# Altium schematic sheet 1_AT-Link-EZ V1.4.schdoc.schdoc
size 309 x 223 mm; Symbol: Artery_A4; Device: Artery_A4; @Page Count: 4; @Create Date: 2024-01-02; @Page Name: AT-Link-EZ V1.4; @Project Name: AT-START-L021; @Update Date: 2024-02-21; @Schematic Name: AT-START-L021_V1.0; @Page No: 1; Company: Artery Technology; Drawed: SD; Version: 1.0; Page Size: A4
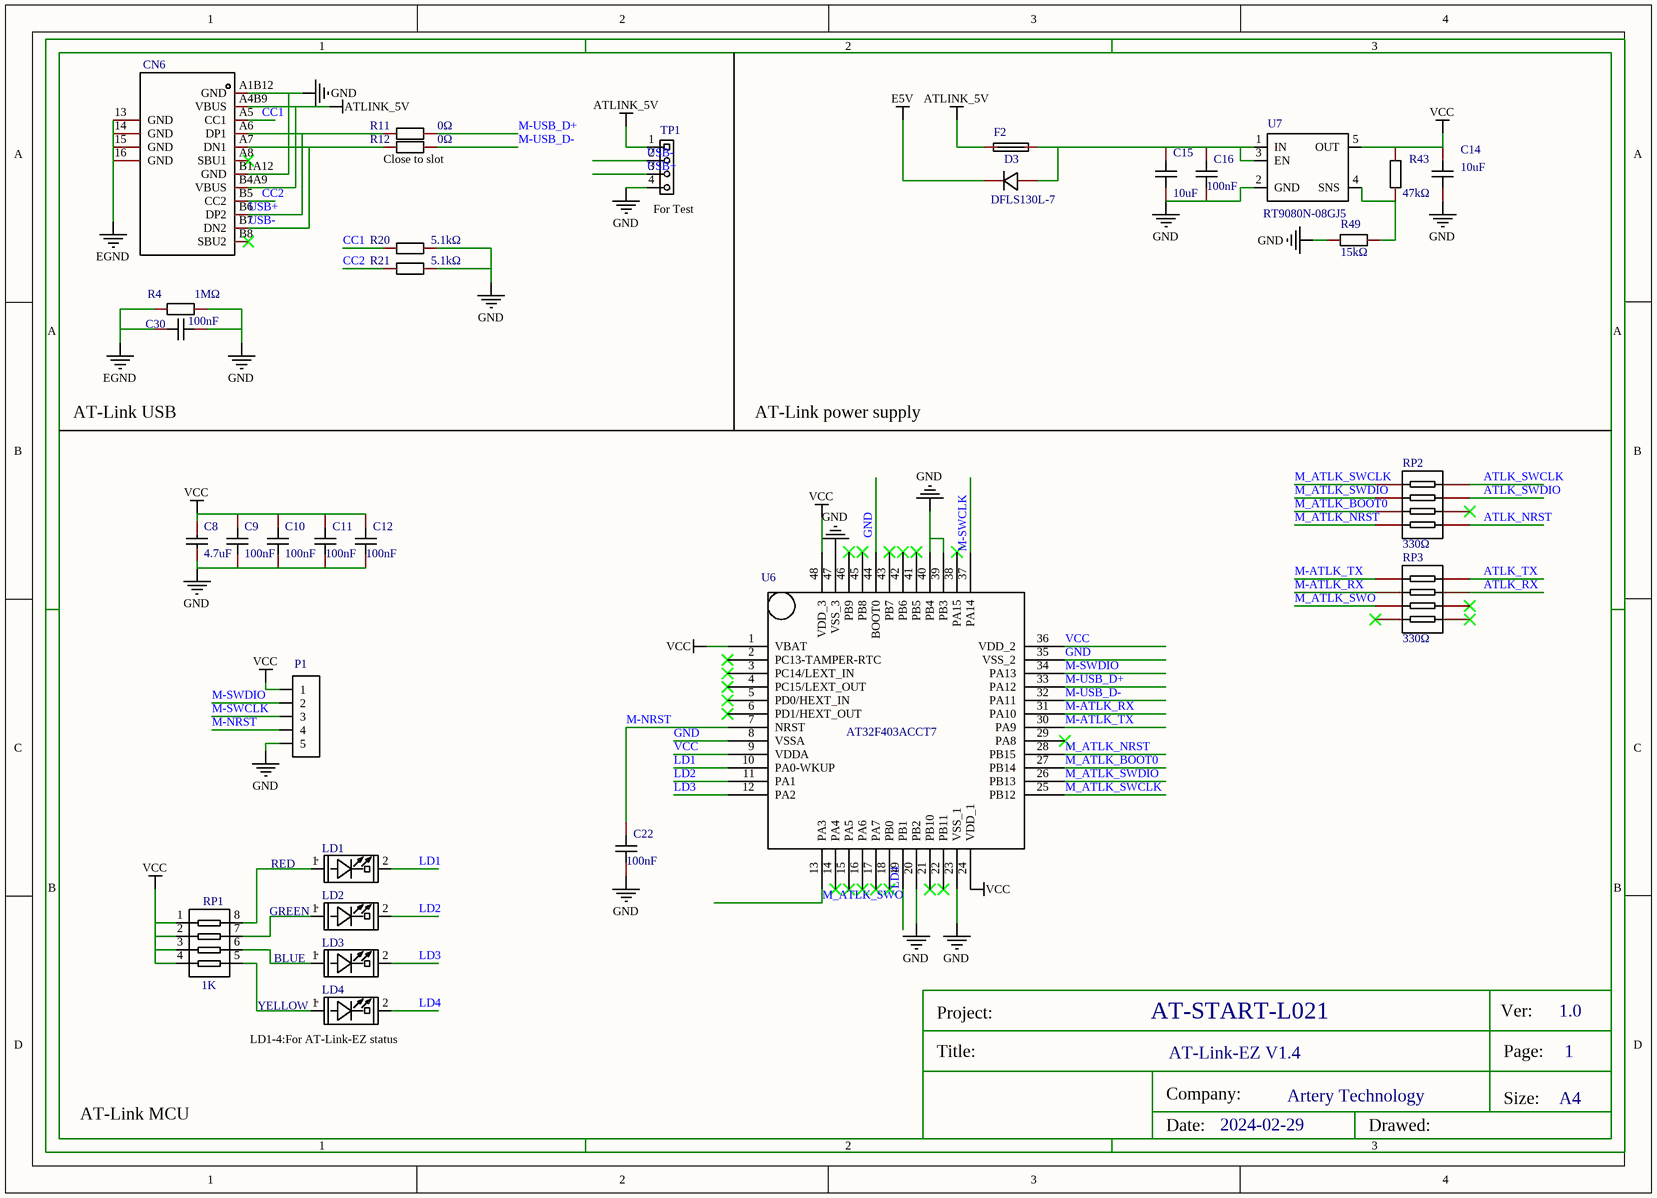
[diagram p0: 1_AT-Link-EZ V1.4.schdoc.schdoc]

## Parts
C8  value 4.7uF  [C0603]  (hidden comment: CL10A475KO8NNNC)
C9  value 100nF  [C0603]  (hidden comment: CC0603KRX7R9BB104)
C10  value 100nF  [C0603]  (hidden comment: CC0603KRX7R9BB104)
C11  value 100nF  [C0603]  (hidden comment: CC0603KRX7R9BB104)
C12  value 100nF  [C0603]  (hidden comment: CC0603KRX7R9BB104)
C14  value 10uF  [C0603]  (hidden comment: CL10A106KP8NNNC)
C15  value 10uF  [C0603]  (hidden comment: CL10A106KP8NNNC)
C16  value 100nF  [C0603]  (hidden comment: CC0603KRX7R9BB104)
C22  value 100nF  [C0603]  (hidden comment: CC0603KRX7R9BB104)
C30  value 100nF  [C0603]  (hidden comment: CC0603KRX7R9BB104)
CN6  TYPEC-304-BCP16  [USB-C-SMD_TYPEC-304-BCP16]  (value not drawn)
D3  DFLS130L-7  [POWERDI-123_L2.8-W1.8-LS3.7-RD]
F2  SMD0603B050TF  [R0603]  (value not drawn)
LD1  RED  [LED0603]
LD2  GREEN  [LED0603]
LD3  BLUE  [LED0603]
LD4  YELLOW  [LED0603]
P1  HDR-M-2.54_1x5  [HDR-M-2.54_1X5]  (value not drawn)
R4  value 1MΩ  [R0603]  (hidden comment: RC0603FR-071ML)
R11  value 0Ω  [R0603]  (hidden comment: 0603WAF0000T5E)
R12  value 0Ω  [R0603]  (hidden comment: 0603WAF0000T5E)
R20  value 5.1kΩ  [R0603]  (hidden comment: 0603WAF5101T5E)
R21  value 5.1kΩ  [R0603]  (hidden comment: 0603WAF5101T5E)
R43  value 47kΩ  [R0603]  (hidden comment: 0603WAF4702T5E)
R49  value 15kΩ  [R0603]  (hidden comment: 0603WAF1502T5E)
RP1  1K  [0603*4,8P4R]
RP2  value 330Ω  [RES-ARRAY-SMD_0603-8P-L3.2-W1.6-BL]  (hidden comment: 4D03WGJ0331T5E)
RP3  value 330Ω  [RES-ARRAY-SMD_0603-8P-L3.2-W1.6-BL]  (hidden comment: 4D03WGJ0331T5E)
TP1  1X4P_2.54F  [HDR1X4 - TOP]  (value not drawn)
U6  AT32F403ACCT7  [LQFP48 - 2]
U7  RT9080N-08GJ5  [SOT-23-5(1)]

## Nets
ATLINK_5V: CN6.A4B9(VBUS) CN6.B4A9(VBUS) F2.1 TP1.1
E5V: D3.1
EGND: C30.2 CN6.13(GND) CN6.14(GND) CN6.15(GND) CN6.16(GND) R4.1
GND: C8.1 C9.1 C10.1 C11.1 C12.1 C14.1 C15.1 C16.1 C22.1 C30.1 CN6.A1B12(GND) CN6.B1A12(GND) P1.5 R4.2 R20.2 R21.2 R49.1 TP1.4 U6.8(VSSA) U6.20(PB2) U6.23(VSS_1) U6.35(VSS_2) U6.39(PB3) U6.40(PB4) U6.44(BOOT0) U6.47(VSS_3) U7.2(GND)
VCC: C8.2 C9.2 C10.2 C11.2 C12.2 C14.2 P1.1 R43.2 RP1.1 RP1.2 RP1.3 RP1.4 U6.1(VBAT) U6.9(VDDA) U6.24(VDD_1) U6.36(VDD_2) U6.48(VDD_3) U7.5(OUT)
ATLK_NRST: RP2.4
ATLK_RX: RP3.2
ATLK_SWCLK: RP2.1
ATLK_SWDIO: RP2.2
ATLK_TX: RP3.1
CC1: CN6.A5(CC1) R20.1
CC2: CN6.B5(CC2) R21.1
LD1: LD1.2(CATHODE) U6.10(PA0-WKUP)
LD2: LD2.2(CATHODE) U6.11(PA1)
LD3: LD3.2(CATHODE) U6.12(PA2)
LD4: LD4.2(CATHODE) U6.19(PB1)
M-ATLK_RX: RP3.7 U6.31(PA10)
M-ATLK_TX: RP3.8 U6.30(PA9)
M-NRST: C22.2 P1.4 U6.7(NRST)
M-SWCLK: P1.3 U6.37(PA14)
M-SWDIO: P1.2 U6.34(PA13)
M-USB_D+: R11.2 U6.33(PA12)
M-USB_D-: R12.2 U6.32(PA11)
M_ATLK_BOOT0: RP2.6 U6.27(PB14)
M_ATLK_NRST: RP2.5 U6.28(PB15)
M_ATLK_SWCLK: RP2.8 U6.25(PB12)
M_ATLK_SWDIO: RP2.7 U6.26(PB13)
M_ATLK_SWO: RP3.6 U6.13(PA3)
USB+: CN6.A6(DP1) CN6.B6(DP2) R11.1 TP1.3
USB-: CN6.A7(DN1) CN6.B7(DN2) R12.1 TP1.2
NetC15_2: C15.2 C16.2 D3.2 F2.2 U7.1(IN) U7.3(EN)
NetLD1_1: LD1.1(ANODE) RP1.8
NetLD2_1: LD2.1(ANODE) RP1.7
NetLD3_1: LD3.1(ANODE) RP1.6
NetLD4_1: LD4.1(ANODE) RP1.5
NetR43_1: R43.1 R49.2 U7.4(SNS)

Not connected (* = marked no-connect by the designer): CN6 A8(SBU1)* B8(SBU2)*; RP2 3*; RP3 3* 4* 5*; U6 2(PC13-TAMPER-RTC)* 3(PC14/LEXT_IN)* 4(PC15/LEXT_OUT)* 5(PD0/HEXT_IN)* 6(PD1/HEXT_OUT)* 14(PA4)* 15(PA5)* 16(PA6)* 17(PA7)* 18(PB0)* 21(PB10)* 22(PB11)* 29(PA8)* 38(PA15)* 41(PB5)* 42(PB6)* 43(PB7)* 45(PB8)* 46(PB9)*

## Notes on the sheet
- (near R12) Close to slot
- (near TP1) For Test
- AT-Link USB
- AT-Link power supply
- (near LD4) LD1-4:For AT-Link-EZ status
- AT-Link MCU
- 2024-02-29

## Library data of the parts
C8 = CL10A475KO8NNNC: Manufacturer: SAMSUNG(三星); Add into BOM: yes; Tolerance: ±10%; Voltage Rated: 16V; Temperature Coefficient: X5R; Description: 容值:4.7uF;精度:±10%;额定电压:16V;温度系数:X5R;; Pin Type: IN
C9-C12 C16 C22 C30 = CC0603KRX7R9BB104: Manufacturer: YAGEO(国巨); Add into BOM: yes; Tolerance: ±10%; Voltage Rated: 50V; Temperature Coefficient: X7R; Description: 容值:100nF;精度:±10%;额定电压:50V;温度系数:X7R;; Pin Type: IN
C14 C15 = CL10A106KP8NNNC: Manufacturer: SAMSUNG(三星); Add into BOM: yes; Tolerance: ±10%; Voltage Rated: 10V; Temperature Coefficient: X5R; Description: 容值:10uF;精度:±10%;额定电压:10V;温度系数:X5R;; Pin Type: IN
CN6 = TYPEC-304-BCP16: 连接器类型:Type-C;标准:USB 3.1;公母:母座;触点数量:16.0;端口数量:1;安装方式:卧贴;额定电流 - 电源:3A;工作温度范围:-25~+85;焊接温度(最大值):260;; Manufacturer: XUNPU(讯普); Add into BOM: yes; Connector Type: Type-C; Gender: 母座; Number of Contacts: 16.0; Number of Ports: 1; Mounting Sytle: 卧贴; Current Rating - Power (Max): 3A; Welding Temperature (Max): 260; Pin Type: IN
D3 = DFLS130L-7_POWERDI-123_L2.8-W1.8-LS3.7-RD: Manufacturer: Diodes Incorporated; Paste Type: expand; Convert to PCB: yes
F2 = SMD0603B050TF: Manufacturer: Brightking Elec (TAIWAN); Manufacturer Part: SMD0603B035TF; Paste Type: expand; Convert to PCB: yes
LD1 = RED: Convert to PCB: yes
LD2 = GREEN: Convert to PCB: yes
LD3 = BLUE: Convert to PCB: yes
LD4 = YELLOW: Convert to PCB: yes
P1 = HDR-M-2.54_1x5: Convert to PCB: yes
R4 = RC0603FR-071ML: 阻值:1MΩ;精度:±1%;功率:100mW;温度系数:±100ppm/;最大工作电压:75V;工作温度范围:-55~+155;; Manufacturer: YAGEO(国巨); Add into BOM: yes; Tolerance: ±1%; Power(Watts): 100mW; Overload Voltage (Max): 75V; Pin Type: IN
R11 R12 = 0603WAF0000T5E: 电阻类型:厚膜电阻;阻值:0Ω;精度:±1%;功率:1/10W;温度系数:-;最大工作电压:75V;工作温度范围:-55~+155;; Manufacturer: UNI-ROYAL(厚声); Add into BOM: yes; Tolerance: ±1%; Power(Watts): 1/10W; Overload Voltage (Max): 75V; Pin Type: IN
R20 R21 = 0603WAF5101T5E: 电阻类型:厚膜电阻;阻值:5.1kΩ;精度:±1%;功率:1/10W;温度系数:±100ppm/;最大工作电压:75V;工作温度范围:-55~+155;; Manufacturer: UNI-ROYAL(厚声); Add into BOM: yes; Tolerance: ±1%; Power(Watts): 1/10W; Overload Voltage (Max): 75V; Pin Type: IN
R43 = 0603WAF4702T5E: 电阻类型:厚膜电阻;阻值:47kΩ;精度:±1%;功率:1/10W;温度系数:±100ppm/;最大工作电压:75V;工作温度范围:-55~+155;; Manufacturer: UNI-ROYAL(厚声); Add into BOM: yes; Tolerance: ±1%; Power(Watts): 1/10W; Overload Voltage (Max): 75V; Pin Type: IN
R49 = 0603WAF1502T5E: 电阻类型:厚膜电阻;阻值:15kΩ;精度:±1%;功率:1/10W;温度系数:±100ppm/;最大工作电压:75V;工作温度范围:-55~+155;; Manufacturer: UNI-ROYAL(厚声); Add into BOM: yes; Tolerance: ±1%; Power(Watts): 1/10W; Overload Voltage (Max): 75V; Pin Type: IN
RP1 = 1K: Convert to PCB: yes
RP2 RP3 = 4D03WGJ0331T5E: Manufacturer: UNI-ROYAL(厚声); Add into BOM: yes; Tolerance: ±5%; Power(Watts): 62.5mW; Number of Resistors: 4; Temperature Coefficient: ±200ppm/℃; Description: 阻值:330Ω;精度:±5%;单个元件功率:62.5mW;电阻器数:4;温度系数:±200ppm/℃;
TP1 = 1X4P_2.54F: Convert to PCB: yes
U6 = AT32F403CGT6: Convert to PCB: yes
U7 = RT9080N-08GJ5_SOT-23-5: Convert to PCB: yes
